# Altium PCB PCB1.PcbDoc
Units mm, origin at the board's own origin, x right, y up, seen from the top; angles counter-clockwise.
Board outline 30.4 x 31.22 mm, 2 copper layers (Top Layer, Bottom Layer); 47 components, 33 nets, 158 pads, 139 vias.
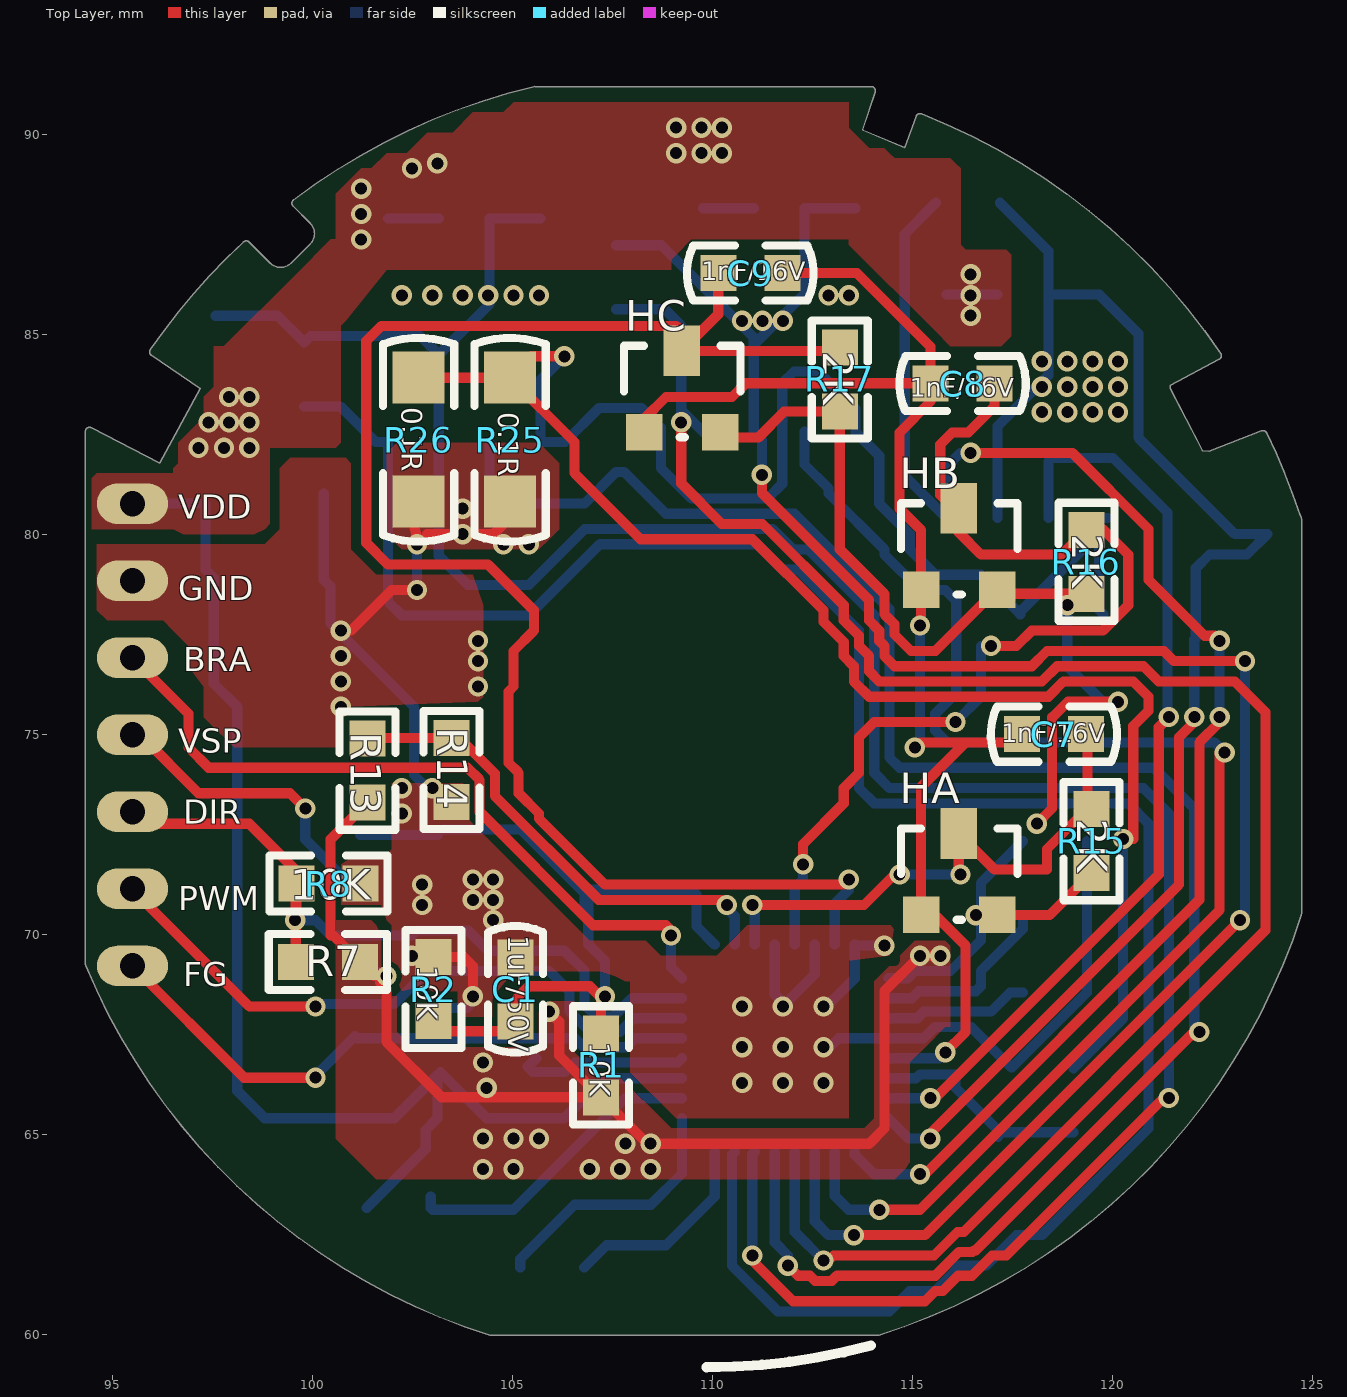
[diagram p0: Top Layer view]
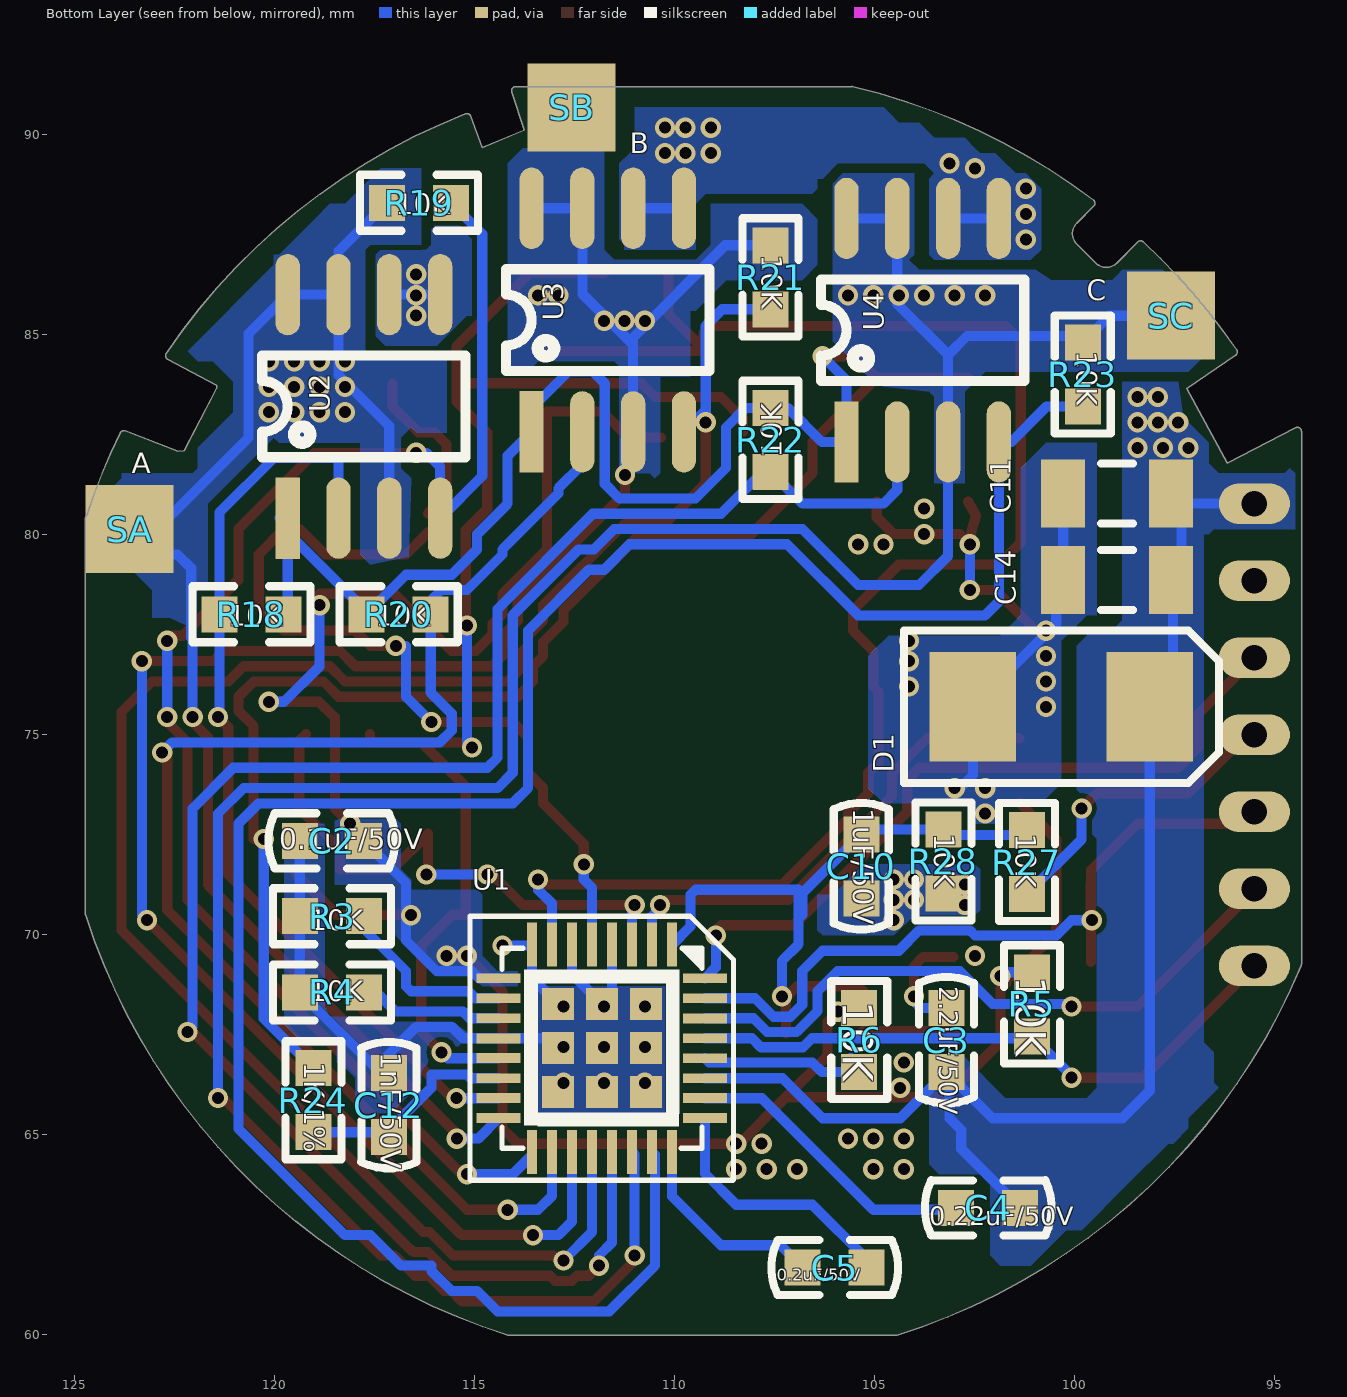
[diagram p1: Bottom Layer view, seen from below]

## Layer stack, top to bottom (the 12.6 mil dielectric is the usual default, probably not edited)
Top Solder: solder mask 0.0102, Solder Resist, Dk 3.5
Top Layer: signal copper 0.0356
Dielectric 1: dielectric 0.32, FR-4, Dk 4.8
Bottom Layer: signal copper 0.0356
Bottom Solder: solder mask 0.0102, Solder Resist, Dk 3.5

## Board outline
94.333,69.224 cw(c94.428,69.263) 94.326,69.263 94.326,82.578 cw(c94.428,82.578) 94.475,82.669 94.474,82.669 94.475,82.669 96.186,81.785 97.199,83.648 95.975,84.48 cw(c96.032,84.564) 95.948,84.622 cw(c109.296,75.438) 98.276,87.315 cw(c98.345,87.24) 98.423,87.306 98.945,86.784 ccw(c98.873,86.712) 98.945,86.784 ccw(c99.206,87.044) 99.466,86.784 99.945,87.263 ccw(c100.017,87.191) 99.945,87.263 ccw(c99.685,87.523) 100.053,87.523 ccw(c99.685,87.523) 99.945,87.783 cw(c100.017,87.856) 99.945,87.784 99.945,87.783 99.518,88.211 cw(c99.59,88.283) 99.528,88.364 cw(c109.296,75.438) 105.538,91.198 cw(c105.562,91.099) 105.581,91.199 113.97,91.199 cw(c113.97,91.097) 114.072,91.097 cw(c113.97,91.097) 114.067,91.065 113.753,90.113 114.812,89.671 115.092,90.455 cw(c115.188,90.421) 115.226,90.516 cw(c109.296,75.438) 122.708,84.529 cw(c122.623,84.471) 122.725,84.471 cw(c122.623,84.471) 122.671,84.381 121.45,83.733 121.45,83.654 122.252,82.1 122.414,82.082 123.73,82.59 cw(c123.767,82.495) 123.859,82.54 cw(c109.296,75.438) 124.696,80.473 cw(c124.626,80.399) 124.728,80.399 124.728,70.518 ccw(c124.626,70.518) 124.728,70.52 124.728,70.518 cw(c124.626,70.518) 124.723,70.487 cw(c109.296,75.438) 114.164,59.985 cw(c114.133,60.082) 114.133,59.98 104.494,59.98 cw(c104.469,60.079) 104.439,59.981 cw(c109.296,75.438)

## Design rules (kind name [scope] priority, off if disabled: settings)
Clearance [All] p1: gap=0.127
PolygonConnect [All] p1: connectstyle=Direct reliefconductorwidth=0.254 reliefentries=4 polygonreliefangle="90 Angle" airgapwidth=0.254
RoutingVias [All] p1: holewidth=0.711 width=1.27 viastyle="Through Hole" minholewidth=0.711 minwidth=1.27 maxholewidth=0.711 maxwidth=1.27
SilkToSilkClearance [All] p1: silktosilkclearance=0.051
SolderMaskExpansion [All] p1: expansion=0.102
Width [All] p1: maxlimit=0.254 minlimit=0.254 preferedwidth=0.254
29 further rules are at their usual default settings.

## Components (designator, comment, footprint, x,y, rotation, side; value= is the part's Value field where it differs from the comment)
C1 "1uF/50V" C0603 101.981,68.326 r180 top
C2 "0.1uF/50V" C0603 118.872,75.438 r90 bottom
C3 "2.2uF/50V" C0603 106.299,67.056 r0 bottom
C4 "0.22uF/50V" C0603 101.854,60.071 r270 bottom
C5 "0.2uF/50V" C0603 106.299,64.77 r90 bottom
C7 "1nF/16V" C0603 118.237,78.105 r90 top
C8 "1nF/16V" C0603 115.951,86.868 r90 top
C9 "1nF/16V" C0603 111.252,83.439 r270 top
C10 "1uF/50V" C0603 102.235,72.009 r180 bottom
C11 "22uF/25V" C1206 98.933,81.026 r180 bottom
C12 "1nF/50V" C0603 114.046,66.04 r180 bottom
C14 "22uF/25V" C1206 98.933,78.867 r180 bottom
D1 "24V/Zener" SMB 100.33,75.692 r180 bottom
HA "HALL_SOT23-3" SOT-23 119.507,70.866 r0 top locked
HB "HALL_SOT23-3" SOT-23 119.507,78.994 r0 top locked
HC "HALL_SOT23-3" SOT-23 112.582,82.931 r0 top locked
R1 "10K" R0603 105.537,65.278 r180 top
R2 "10K" R0603 101.346,67.183 r180 top
R3 "10K" R0603 120.015,72.136 r90 bottom
R4 "10K" R0603 120.015,70.231 r90 bottom
R5 "10K" R0603 102.743,66.802 r0 bottom
R6 "10K" R0603 107.061,65.913 r0 bottom
R7 "" R0603 98.933,70.993 r90 top
R8 "10K" R0603 101.854,69.596 r270 top
R13 "" R0603 99.695,72.644 r180 top
R14 "" R0603 105.156,75.565 r0 top
R15 "2K" R0603 121.158,73.787 r0 top
R16 "2K" R0603 121.031,80.772 r0 top
R17 "2K" R0603 111.506,82.423 r180 top
R18 "10K" R0603 119.126,76.327 r270 bottom
R19 "10K" R0603 114.935,86.614 r270 bottom
R20 "10K" R0603 115.443,76.327 r270 bottom
R21 "10K" R0603 105.918,87.884 r180 bottom
R22 "10K" R0603 105.918,83.82 r180 bottom
R23 "10K" R0603 101.473,82.55 r0 bottom
R24 "1K/1%" R0603 117.348,67.31 r180 bottom
R25 "0.1R" R1206 107.188,82.296 r0 top
R26 "0.1R" R1206 104.902,82.296 r0 top
R27 "10K" R0603 102.87,70.358 r0 bottom
R28 "10K" R0603 101.6,73.279 r180 bottom
SA "" cp1 129.921,80.137 r0 top
SB "" cp1 118.872,90.678 r0 top
SC "" cp1 103.886,85.471 r0 top
U1 "SDC9270_QFN32" "QFN32 (5*5)" 111.887,72.39 r90 bottom
U2 "MOS" SOP-8 123.571,83.058 r0 bottom
U3 "MOS" SOP-8 117.475,85.217 r0 bottom
U4 "MOS" SOP-8 109.601,84.963 r0 bottom

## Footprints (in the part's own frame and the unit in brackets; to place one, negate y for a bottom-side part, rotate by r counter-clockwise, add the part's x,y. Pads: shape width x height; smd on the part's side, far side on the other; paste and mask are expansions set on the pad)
C0603 [mm]
  rect 0.9x0.9 smd: 1(-3.096,0.496) 2(-3.096,-1.104)
  silkscreen extent -3.78,-1.88 -2.41,1.28
C1206 [mm] "Chip Capacitor, Body 3.2x1.6mm, IPC High Density"
  rect 1.1x1.7 smd: 1(-1.35,0) 2(1.35,0)
  silkscreen extent -0.4,-0.75 0.4,0.75, body extent -1.7,-0.9 1.7,0.9, height 1.3
cp1 [mm]
  rect 2.2x2.2 smd far side: 1(-6.3,0)
"QFN32 (5*5)" [mm]
  rect 1.1x0.25 smd: 1(-2.643,-1.828) 2(-2.643,-1.328) 3(-2.643,-0.828) 4(-2.643,-0.328) 5(-2.643,0.172) 6(-2.643,0.672) 7(-2.643,1.172) 8(-2.643,1.672) 17(-7.823,1.672) 18(-7.823,1.172) 19(-7.823,0.672) 20(-7.823,0.172) 21(-7.823,-0.328) 22(-7.823,-0.828) 23(-7.823,-1.328) 24(-7.823,-1.828)
  rect 0.25x1.1 smd: 9(-3.483,2.512) 10(-3.983,2.512) 11(-4.483,2.512) 12(-4.983,2.512) 13(-5.483,2.512) 14(-5.983,2.512) 15(-6.483,2.512) 16(-6.983,2.512) 25(-6.983,-2.648) 26(-6.483,-2.648) 27(-5.983,-2.648) 28(-5.483,-2.648) 29(-4.983,-2.648) 30(-4.483,-2.648) 31(-3.983,-2.648) 32(-3.483,-2.648)
  rect 0.8x0.8 smd: 33(-6.333,-1.178) 33(-6.333,-0.078) 33(-6.333,1.022) 33(-5.233,-1.178) 33(-5.233,-0.078) 33(-5.233,1.022) 33(-4.133,-1.178) 33(-4.133,-0.078) 33(-4.133,1.022)
  silkscreen extent -8.53,-3.36 -1.93,3.22
R0603 [mm]
  rect 0.9x0.9 smd: 1(-1.679,-0.653) 2(-1.679,-2.253)
  silkscreen extent -2.38,-2.93 -0.98,0.02
R1206 [mm]
  rect 1.3x1.3 smd: 1(-2.244,-1.475) 2(-2.244,1.625)
  silkscreen extent -3.13,-2.47 -1.35,2.62
SMB [mm]
  rect 2.159x2.743 smd: 1(-2.21,0) 2(2.21,0)
  silkscreen extent -3.94,-1.91 3.94,1.91
SOP-8 [mil]
  rect 24x80 smd: 1(-153.56,104.3)
  oval 24x80 smd: 2(-203.56,104.3) 3(-253.56,104.3) 4(-303.56,104.3) 5(-303.56,-115.7) 6(-253.56,-115.7) 7(-203.56,-115.7) 8(-153.56,-115.7)
  silkscreen extent -329,-56 -129,44
SOT-23 [mil]
  rect 36x36 smd: 1(-93.79,-14.61) 3(-168.79,-14.61)
  rect 36x50 smd: 2(-131.79,65.39)
  silkscreen extent -189,-20 -74,70

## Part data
C1 C7 C8 C9 C10 C11 C12 C14: library part C0603, "C0603"
C2 C4 C5: library part C0805, "C0805"
C3: library part C1206, "C1206"
D1: library part Zener_SOD-123, "Zener Diode"
R1 R2 R3 R4 R5 R6 R7 R8 R13 R14 R15 R16 R17 R24 R27 R28: library part R0603, "R0603"
R18 R19 R20 R21 R22 R23: library part R1_0603
R25 R26: library part R2512
SA SB SC: library part CON1, "Connector"

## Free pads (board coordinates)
  oval 1.778x1.016 hole 0.635: 1(95.504,69.215) 1(95.504,71.141) 1(95.504,73.067) 1(95.504,74.993) 1(95.504,76.92) 1(95.504,78.846) 1(95.504,80.772)

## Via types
v1: diameter 0.508, hole 0.3, Top Layer to Bottom Layer, 139 vias

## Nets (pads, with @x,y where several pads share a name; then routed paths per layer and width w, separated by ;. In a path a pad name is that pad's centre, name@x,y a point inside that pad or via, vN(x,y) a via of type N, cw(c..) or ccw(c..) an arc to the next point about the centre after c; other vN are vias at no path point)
BRAKE: pad.1@95.504,76.92 U1.32 | length 18.6
  Top Layer w0.254: pad.1@95.504,76.92 96.901,75.523 96.901,74.676 97.409,74.168 103.88,74.168 104.181,73.867 104.181,73.067 107.017,70.231 108.839,70.231 108.966,70.104 v1(108.966,69.977)
  Bottom Layer w0.254: v1(108.966,69.977) 108.966,69.18 U1.32
CP1: C5.1 U1.24 | length 5.1
  Bottom Layer w0.254: C5.1 107.351,62.23 108.839,62.23 110.059,63.45 U1.24
CP2: C5.2 U1.25 | length 6.5
  Bottom Layer w0.254: C5.2 105.195,61.888 106.553,63.246 108.458,63.246 109.239,64.027 U1.25
DIR: pad.1@95.504,73.067 R7.1 R8.2 U1.31 | length 19.4
  Top Layer w0.254: pad.1@95.504,73.067 95.8,72.771 98.425,72.771 99.586,71.61 R7.1 ; v1(99.568,70.358) 99.601,70.391 R8.2
  Bottom Layer w0.254: v1(99.568,70.358) 100.076,70.358 100.457,69.977 102.489,69.977 102.616,70.104 103.886,70.104 104.394,69.596 106.299,69.596 106.807,69.088 106.807,68.243 107.105,67.945 107.525,67.945 107.987,68.407 U1.31
FG: pad.1@95.504,69.215 R5.1 U1.29 | length 15.6
  Top Layer w0.254: pad.1@95.504,69.215 98.298,66.421 v1(100.076,66.421)
  Bottom Layer w0.254: v1(100.076,66.421) 100.076,66.467 R5.1 101.112,67.407 106.565,67.407 106.789,67.183 107.841,67.183 108.065,67.407 U1.29
GHA: R19.1 U1.17 U2.4 | length 38
  Top Layer w0.254: v1(115.189,64.008) 115.316,64.008 122.174,70.866 122.174,74.803 122.682,75.311 v1(122.682,75.438) ; v1(116.459,82.042) 118.999,82.042 120.904,80.137 120.904,78.867 122.301,77.47 122.555,77.47 v1(122.682,77.343)
  Bottom Layer w0.254: U1.17 113.559,64.495 114.046,64.008 v1(115.189,64.008) ; R19.1 114.808,87.513 114.808,81.461 U2.4 115.86,81.697 116.205,82.042 v1(116.459,82.042) ; v1(122.682,75.438) v1(122.682,77.343)
GHB: R21.2 U1.20 U3.4 | length 47.3
  Top Layer w0.254: v1(109.22,82.804) 109.22,81.28 110.236,80.264 111.252,80.264 113.284,78.232 113.284,77.851 113.665,77.47 113.665,77.216 113.919,76.962 113.919,76.581 114.173,76.327 118.237,76.327 118.618,76.708 120.777,76.708 121.158,76.327 123.063,76.327 123.825,75.565 123.825,70.104 116.284,62.563 116.126,62.563 115.539,61.976 113.03,61.976 v1@112.903,61.849 ; v1@112.649,61.849 v1(112.776,61.849)
  Bottom Layer w0.254: R21.2 108.806,85.631 109.22,85.217 109.22,83.112 ; v1(109.22,82.804) 109.22,83.112 ; U3.4 109.22,83.112 ; U1.20 112.059,62.566 v1(112.776,61.849)
GHC: R23.1 U1.23 U4.4 | length 54.9
  Bottom Layer w0.254: R23.1 100.693,83.203 101.582,82.314 U4.4 101.89,78.323 102.235,77.978 105.41,77.978 107.188,79.756 111.125,79.756 111.76,79.121 112.141,79.121 113.665,77.597 113.665,73.66 114.046,73.279 120.396,73.279 120.904,72.771 120.904,65.151 118.237,62.484 117.602,62.484 116.84,61.722 116.078,61.722 116.078,61.595 115.57,61.087 114.935,61.087 114.427,60.579 111.633,60.579 110.49,61.722 110.49,64.498 U1.23
GLA: R18.2 U1.15 U2.2 | length 23.3
  Top Layer w0.254: v1(115.449,65.907) 115.564,65.907 121.158,71.501 121.158,75.184 v1(121.412,75.438)
  Bottom Layer w0.254: U1.15 v1(115.449,65.907) ; U2.2 118.4,81.824 118.491,81.915 120.015,81.915 121.379,80.551 R18.2 v1@121.379,75.344
GLB: R20.1 U1.18 U3.2 | length 35.1
  Top Layer w0.254: v1(114.173,63.119) 115.189,63.119 122.682,70.612 122.682,74.549 v1(122.809,74.549)
  Bottom Layer w0.254: U3.2 112.304,81.752 112.903,81.153 112.903,81.026 114.3,79.629 114.3,79.502 115.189,78.613 115.824,78.613 116.096,78.341 R20.1 116.096,76.047 115.57,75.521 115.57,75.101 115.868,74.803 122.555,74.803 v1(122.809,74.549) ; U1.18 113.059,63.471 113.411,63.119 v1(114.173,63.119)
GLC: R22.2 U1.21 U4.2 | length 46.8
  Top Layer w0.254: v1(111.887,61.722) 112.141,61.468 112.439,61.468 112.566,61.341 112.986,61.341 113.113,61.468 115.57,61.468 116.163,62.061 116.506,62.061 116.548,62.103 116.586,62.103 122.174,67.691 v1(122.174,67.564)
  Bottom Layer w0.254: U4.2 104.43,81.117 104.775,80.772 106.802,80.772 R22.2 107.79,81.567 108.839,80.518 112.045,80.518 114.427,78.136 114.427,74.422 114.681,74.168 121.031,74.168 122.047,73.152 122.047,67.691 v1(122.174,67.564) ; U1.21 111.559,62.304 111.887,61.976 v1(111.887,61.722)
GND: 
HA: C7.2 HA.2 R15.1 U1.3 | length 13.8
  Top Layer w0.254: v1@111.125,70.739 113.792,70.739 114.554,71.501 v1(114.681,71.501) ; v1@116.159,71.547 HA.2@116.159,72.518 ; HA.2 HA.2@116.159,72.518 ; C7.2@119.214,75.009 119.38,74.843 119.38,73.152 118.364,72.136 118.364,71.628 117.049,71.628 HA.2@116.159,72.518
  Bottom Layer w0.254: v1(110.998,70.739) 111.059,70.678 U1.3 ; v1(114.681,71.501) v1(116.205,71.501)
HB: C8.2 HB.2 R16.1 U1.5 | length 24.9
  Top Layer w0.254: v1(112.268,71.755) 112.268,72.263 113.284,73.279 113.284,73.66 113.665,74.041 113.665,74.93 114.046,75.311 v1(116.078,75.311) ; HB.2@116.159,80.056 116.713,79.502 118.735,79.502 R16.1 119.779,80.119 120.396,79.502 120.396,78.232 119.761,77.597 117.983,77.597 117.602,77.216 v1(116.967,77.216) ; HB.2@116.159,80.528 115.697,80.99 115.697,82.252 115.995,82.55 116.398,82.55 117.055,83.207 C8.2
  Bottom Layer w0.254: U1.5 112.059,71.165 112.268,71.374 v1(112.268,71.755) ; v1(116.078,75.311) 116.713,75.946 v1@116.713,77.216
HC: C9.2 HC.2 R17.2 U1.7 | length 40.8
  Top Layer w0.254: C9.2 110.148,85.506 HC.2@109.273,84.631 ; R17.2 113.101,84.592 HC.2 HC.2@109.273,84.631 ; v1(113.411,71.374) 113.284,71.247 107.315,71.247 105.664,72.898 105.664,73.025 105.156,73.533 105.156,74.041 104.902,74.295 104.902,76.073 105.029,76.2 105.029,77.089 105.537,77.597 105.537,78.105 104.394,79.248 101.89,79.248 101.346,79.792 101.346,84.836 101.727,85.217 109.093,85.217 109.273,85.037 HC.2@109.273,84.631
  Bottom Layer w0.254: U1.7 113.059,70.768 113.411,71.12 v1(113.411,71.374)
ILIMIT: C12.2 R24.2 U1.14 | length 5.5
  Bottom Layer w0.254: U1.14 115.091,66.407 115.189,66.504 116.078,66.504 116.078,66.167 117.142,65.103 C12.2 ; C12.2@117.262,65.057 R24.2
ISENSE: R18.1 R20.2 R22.1 R24.1 R25.2 R26.2 U2.1 U3.1 U4.1 | length 63
  Top Layer w0.254: R26.2 R25.2 ; v1(106.299,84.455) 105.478,84.455 R25.2 ; v1(120.269,72.39) 120.523,72.39 120.523,75.215 120.904,75.596 120.904,75.946 120.523,76.327 118.776,76.327 118.395,75.946 113.919,75.946 113.538,76.327 113.538,76.708 113.284,76.962 113.284,77.312 112.776,77.82 112.776,78.105 110.998,79.883 108.204,79.883 106.553,81.534 106.553,82.312 R25.2
  Bottom Layer w0.254: v1(106.299,84.455) 105.7,83.856 U4.1 106.317,82.314 107.17,83.167 R22.1 108.222,83.167 108.712,82.677 108.712,81.661 109.474,80.899 111.379,80.899 111.746,81.266 111.746,83.779 112.041,84.074 112.649,84.074 113.574,83.149 U3.1 114.173,81.969 114.173,80.772 114.935,80.01 114.935,79.629 115.57,78.994 116.713,78.994 R20.2@117.696,78.011 ; R20.2 R20.2@117.696,78.011 ; R24.1 120.269,67.899 v1(120.269,72.39) ; R18.1 119.67,78.115 U2.1@119.67,80.046 ; U2.1@119.87,80.409 U2.1 U2.1@119.67,80.046 ; R20.2@117.696,78.011 117.696,78.072 U2.1@119.67,80.046
LEAD: R13.2 R14.1 U1.2 | length 12.1
  Top Layer w0.254: R13.2 101.389,74.912 R14.1 103.675,74.912 104.562,74.025 104.562,73.461 107.157,70.866 110.236,70.866 v1(110.363,70.739)
  Bottom Layer w0.254: v1(110.363,70.739) 110.363,70.656 110.559,70.46 U1.2
MODE: R3.2 U1.10 | length 4.6
  Bottom Layer w0.254: U1.10 114.985,68.407 115.159,68.58 116.586,68.58 116.713,68.707 116.713,69.088 117.762,70.137 R3.2
NetP1_3: pad.1@95.504,74.993 R27.1 | length 7.8
  Top Layer w0.254: pad.1@95.504,74.993 95.695,74.993 97.155,73.533 99.441,73.533 v1(99.822,73.152)
  Bottom Layer w0.254: v1(99.822,73.152) 99.822,72.38 R27.1
NFLT: R6.1 U1.28 | length 4.4
  Bottom Layer w0.254: R6.1@105.596,66.907 105.382,66.693 105.509,66.566 106.317,66.566 106.553,66.802 109.134,66.802 U1.28
PGND: C7.1 C8.1 C9.1 HA.3 HB.3 HC.3 U1.13 | length 36.3
  Top Layer w0.254: HC.3 108.295,82.895 108.839,83.439 110.49,83.439 110.831,83.78 C8.1@115.455,83.78 ; C9.1 113.617,86.535 115.455,84.697 C8.1@115.455,83.78 ; v1(115.062,74.676) 115.189,74.803 116.332,74.803 ; v1@115.22,77.755 HB.3 115.22,80.106 114.681,80.645 114.681,82.55 115.455,83.324 C8.1 C8.1@115.455,83.78 ; v1(115.824,67.056) 116.332,67.564 116.332,69.723 115.56,70.495 HA.3 115.22,73.691 116.332,74.803 ; C7.1@117.614,75.009 117.614,74.803 116.332,74.803
  Bottom Layer w0.254: U1.13 115.675,66.907 v1(115.824,67.056) ; v1(115.062,74.676) 115.189,74.803 v1(115.189,77.724)
PWM: pad.1@95.504,71.141 U1.30 | length 16.4
  Top Layer w0.254: pad.1@95.504,71.141 95.504,71.12 98.425,68.199 v1(100.076,68.199)
  Bottom Layer w0.254: v1(100.076,68.199) 100.141,68.264 102.046,68.264 102.87,69.088 105.918,69.088 106.426,68.58 106.426,68.085 106.947,67.564 107.683,67.564 108.026,67.907 U1.30
PWMIN: 
SA: R19.2 SA.1 U1.16 U2.3 U2.7 U2.8 | length 39
  Top Layer w0.254: v1(115.443,64.897) 115.316,64.897 121.666,71.247 121.666,74.93 122.047,75.311 v1(122.047,75.438)
  Bottom Layer w0.254: U1.16 114.909,64.897 v1(115.443,64.897) ; U2.3 117.13,82.713 118.4,83.983 U2.7 ; R19.2 118.4,87.081 U2.7 ; v1(122.047,75.438) 122.047,77.379 122.083,77.415 122.083,79.157 122.428,79.502 123.367,79.502 123.875,80.01 123.063,80.01 120.65,82.423 120.65,85.017 U2.8 U2.7
  other v1: 118.237,83.058 118.872,83.058 119.507,83.058 120.142,83.058 118.237,83.693 118.872,83.693 119.507,83.693 120.142,83.693 118.237,84.328 118.872,84.328 119.507,84.328 120.142,84.328
SB: R21.1 SB.1 U1.19 U3.3 U3.7 U3.8 | length 50.6
  Top Layer w0.254: v1(111.238,81.494) 111.238,81.04 113.919,78.359 113.919,77.851 114.173,77.597 114.173,77.343 114.3,77.216 114.3,76.962 114.554,76.708 117.983,76.708 118.364,77.089 121.285,77.089 121.539,76.835 v1(123.317,76.835) ; v1(113.538,62.484) 115.316,62.484 v1(123.19,70.358)
  Bottom Layer w0.254: R21.1 108.73,87.231 111.034,84.927 111.034,84.745 ; v1(111.238,81.494) 111.238,82.365 U3.3 111.034,84.745 ; U1.19 112.559,62.828 112.903,62.484 v1(113.538,62.484) ; U3.8 U3.7 112.304,86.015 111.034,84.745 ; v1(123.19,70.358) 123.317,70.485 v1(123.317,76.835)
  other v1: 110.744,85.344 111.252,85.344 111.76,85.344 112.903,85.979 113.411,85.979
SC: R23.2 SC.1 U1.22 U4.3 U4.7 U4.8 | length 63.7
  Top Layer w0.254: v1(110.998,61.976) 110.998,61.849 112.014,60.833 115.316,60.833 115.57,61.087 115.759,61.087 116.14,61.468 116.49,61.468 116.998,61.976 117.348,61.976 121.412,66.04 v1(121.412,65.913)
  Bottom Layer w0.254: SC.1 99.126,85.471 R23.2 99.954,84.963 102.689,84.963 103.16,84.491 ; U4.8 U4.7 104.43,85.761 103.16,84.491 ; v1(110.998,61.976) 110.998,64.506 U1.22 ; v1(121.412,65.913) 121.412,73.025 120.777,73.66 114.427,73.66 114.046,74.041 114.046,77.978 112.395,79.629 112.014,79.629 111.506,80.137 106.807,80.137 105.41,78.74 103.886,78.74 103.16,79.466 U4.3 103.16,84.491
  other v1: 102.235,85.979 102.997,85.979 103.759,85.979 104.394,85.979 105.029,85.979 105.664,85.979
SGND: C1.2 C2.1 C3.2 C10.2 C11.1 C12.1 C14.1 D1.1 pad.1@95.504,78.846 R2.2 R3.1 R4.1 R8.1 R14.2 R25.1 R26.1 R28.2 U1.4 U1.6 U1.8 U1.12 U1.33 | length 36.2
  Top Layer w0.254: v1(100.711,77.597) 100.965,77.597 101.981,78.613 v1(102.616,78.613) ; v1(102.616,79.756) 102.658,79.798 102.466,80.477 R26.1 ; 102.87,80.01 v1(103.759,80.01) 104.521,80.01 104.944,80.433 R25.1 ; R2.2 103.792,69.436 104.013,69.215 v1(104.013,68.453)
  Bottom Layer w0.254: C11.1 C14.1 100.457,78.693 100.457,77.775 D1.1 102.54,73.99 102.87,73.66 v1(102.997,73.66) ; v1(102.616,78.613) v1(102.616,79.756) ; C3.2 103.847,68.16 104.013,68.326 v1(104.013,68.453) ; U1.4 111.559,68.507 111.809,68.257 112.559,69.007 U1.6 ; U1.33@112.909,67.157 113.159,67.407 U1.12 115.286,67.407 115.57,67.691 116.459,67.691 117.475,66.675 117.485,66.675 R4.1 ; U1.33@112.909,68.257 113.559,68.907 U1.8 113.583,69.723 v1(114.3,69.723) ; R4.1@119.368,68.558 C2.1
  other v1: 110.744,66.294 111.76,66.294 112.776,66.294 110.744,67.183 111.76,67.183 112.776,67.183 110.744,68.199 111.76,68.199 112.776,68.199 102.489,69.469 104.521,70.358 102.743,70.739 104.013,70.866 104.521,70.866 102.743,71.247 104.013,71.374 104.521,71.374 102.235,73.025 102.235,73.66 100.711,75.692 104.14,76.2 100.711,76.327 104.14,76.835 100.711,76.962 104.14,77.343 104.775,79.756 105.41,79.756 103.759,80.645
SREF: C1.1 C10.1 R1.2 R2.1 R27.2 R28.1 U1.1 | length 20.1
  Top Layer w0.254: R2.1@102.898,67.582 C1.1@105.301,67.582 ; C1.1 105.077,68.374 105.41,68.707 106.934,68.707 107.188,68.453 v1(107.315,68.453) 107.216,68.354 R1.2
  Bottom Layer w0.254: R27.2@101.191,72.484 R28.1@103.137,72.484 ; R28.1 105.21,72.626 C10.1 106.807,71.029 106.807,70.485 ; v1(107.315,68.453) 107.315,69.342 106.898,69.759 106.898,71.12 109.474,71.12 109.601,70.993 109.601,70.205 U1.1
TEST: R4.2 U1.11 | length 3.6
  Bottom Layer w0.254: U1.11 115.12,67.907 115.285,68.072 116.967,68.072 117.447,68.552 R4.2
VCP: C4.2 U1.26 | length 7.7
  Bottom Layer w0.254: C4.2@102.958,63.452 C4.2 103.005,63.119 105.029,63.119 107.817,65.907 U1.26
VDD: C3.1 C4.1 C11.2 C14.2 D1.2 pad.1@95.504,80.772 U1.27 U2.5 U2.6 U3.5 U3.6 U4.5 U4.6 | length 37.5
  Bottom Layer w0.254: pad.1@95.504,80.772 97.329,80.772 97.329,79.121 97.536,78.914 97.536,76.276 D1.2 98.12,66.091 98.806,65.405 102.049,65.405 C3.1@103.124,66.48 ; C4.1 102.834,64.643 102.834,65.115 103.124,65.405 C3.1@103.124,66.48 ; U4.5 U4.6 ; U1.27 107.301,66.407 106.299,65.405 104.358,65.405 C3.1 C3.1@103.124,66.48 ; U3.5 U3.6 ; U2.5 U2.6
  other v1: 97.155,82.169 97.79,82.169 98.425,82.169 97.409,82.804 97.917,82.804 98.425,82.804 97.917,83.439 98.425,83.439 116.459,85.471 116.459,85.979 116.459,86.505 101.219,87.376 101.219,88.011 101.219,88.646 102.489,89.154 103.124,89.281 109.093,89.535 109.728,89.535 110.236,89.535 109.093,90.17 109.728,90.17 110.236,90.17
VREF: C2.2 HA.1 HB.1 HC.1 R1.1 R5.2 R6.2 R7.2 R13.1 R15.2 R16.2 R17.1 U1.9 | length 60.6
  Top Layer w0.254: R13.1 100.457,72.38 100.457,69.977 100.523,69.977 R7.2 101.539,68.961 v1(101.854,68.961) ; v1@101.696,68.803 101.854,68.646 101.854,67.31 103.233,65.931 R1.1 ; v1(105.918,68.072) 106.172,67.818 106.172,66.975 R1.1 ; HC.1@110.337,82.423 111.146,82.423 111.799,83.076 R17.1 113.185,79.632 114.3,78.517 114.3,78.009 114.554,77.755 114.554,77.501 114.966,77.089 115.57,77.089 HB.1@117.104,78.623 ; v1(115.697,69.469) v1(115.189,69.469) 114.3,68.58 114.3,65.151 113.919,64.77 108.377,64.77 R1.1 ; v1@116.596,70.495 HA.1 ; HA.1@117.135,70.485 118.43,70.485 R15.2 ; HB.1@117.229,78.519 118.872,78.519 ; v1(118.11,72.771) 118.491,73.152 118.491,75.438 118.51,75.438 118.891,75.819 v1(120.142,75.819) ; v1(118.872,78.232) R16.2@119.065,78.232
  Bottom Layer w0.254: R5.2 101.76,69.055 v1(101.854,68.961) ; U1.9 114.881,68.907 115.062,69.088 115.951,69.088 116.713,69.85 116.713,71.287 C2.2 ; v1(118.872,78.232) 118.872,76.708 119.761,75.819 v1(120.142,75.819)
  other v1: 104.267,64.135 105.029,64.135 106.934,64.135 107.696,64.135 108.458,64.135 107.823,64.77 108.458,64.77 104.267,64.897 105.029,64.897 105.664,64.897 104.358,66.167 104.267,66.802 116.586,70.485

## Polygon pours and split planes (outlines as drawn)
SGND on Bottom Layer "SGND" (solid, remove dead copper, pour order 30): 100.711,82.169 101.219,81.661 101.346,81.534 101.346,77.978 101.854,77.47 104.013,77.47 104.521,77.47 104.648,77.47 105.029,77.089 105.156,76.962 105.156,73.787 105.156,73.66 104.775,73.279 102.616,73.279 102.616,72.771 101.854,72.771 101.854,73.279 100.838,73.279 100.457,73.66 100.33,73.787 100.33,77.343 99.695,77.978 99.441,77.978 99.441,82.296 100.711,82.296 101.346,81.661 101.346,81.534
VREF on Bottom Layer "VREF" (solid, remove dead copper, pour order 24): 113.919,68.707 114.808,68.707 114.935,68.834 115.062,68.961 115.951,68.961 116.84,69.85 117.094,70.104 117.094,70.993 117.094,71.247 118.491,71.247 118.491,73.025 118.364,72.898 116.967,72.898 116.84,72.771 116.84,71.628 116.586,71.374 116.586,71.12 115.951,71.12 115.824,70.993 115.951,71.12 114.935,71.12 114.808,70.993 114.808,70.485 114.808,69.469 114.681,69.342 114.427,69.088 113.919,69.088
SGND on Bottom Layer "SGND" (solid, remove dead copper, pour order 22): 105.283,71.755 106.045,70.993 106.426,70.993 106.426,70.104 106.299,69.977 104.648,69.977 104.521,69.977 104.013,70.485 102.489,70.485 102.362,70.612 102.362,71.628 102.489,71.755 105.283,71.755
SGND on Bottom Layer "SGND" (solid, remove dead copper, pour order 20): 113.359,68.707 113.411,68.655 113.411,65.532 110.236,65.532 110.236,68.707 111.76,68.707 113.359,68.707 113.411,68.759
VDD on Bottom Layer "VDD" (solid, remove dead copper, pour order 12): 98.806,83.82 98.806,77.851 99.06,77.597 99.314,77.597 99.568,77.597 99.949,77.216 99.949,73.66 99.949,72.898 99.568,72.517 99.441,72.39 99.441,72.009 99.441,66.167 99.695,65.913 101.346,65.913 101.727,65.913 102.743,66.929 103.632,66.929 103.632,64.262 103.378,64.008 102.362,64.008 102.108,63.754 102.108,62.611 102.108,61.976 101.854,61.722 101.346,61.722 101.092,61.722 100.203,62.611 99.822,62.611 98.679,63.754 97.663,64.77 97.536,64.77 97.155,65.151 97.155,65.278 97.155,65.405 96.393,66.167 96.52,66.294 96.52,66.929 96.52,67.056 96.647,67.183 96.774,67.31 96.774,80.01 96.647,80.01 96.52,80.137 94.488,80.137 94.488,81.534 94.615,81.661 94.742,81.534 96.393,81.534 96.647,81.788 96.647,82.169 96.647,82.296 97.028,82.677 97.282,82.931 97.409,83.82
VDD on Bottom Layer "VDD" (solid, remove dead copper, pour order 10): 111.252,87.122 111.252,87.249 111.379,87.376 111.379,89.281 111.125,89.535 110.998,89.662 110.998,90.678 105.664,90.678 105.537,90.678 105.41,90.678 105.156,90.678 104.775,90.678 104.648,90.551 104.394,90.297 104.013,90.297 103.886,90.297 103.505,89.916 102.997,89.916 102.743,89.916 102.489,89.662 102.362,89.535 102.235,89.535 101.981,89.535 101.854,89.408 101.473,89.027 101.219,89.027 100.838,88.646 100.838,87.376 100.838,87.122 101.092,86.868 101.346,86.868 103.505,86.868 103.632,86.995 103.632,87.249 103.632,88.9 103.505,89.027 103.759,89.281 103.886,89.281 105.918,89.281 106.299,88.9 106.426,88.9 106.426,88.646 106.553,88.519 109.093,88.519 109.22,88.519 109.347,88.392 109.474,88.265 109.474,87.122
SC on Bottom Layer "SC" (solid, remove dead copper, pour order 8): 105.791,89.027 106.045,88.773 106.045,84.836 105.918,84.709 105.029,83.82 104.775,83.693 103.632,83.566 103.505,83.439 103.505,81.28 102.743,81.28 102.743,83.566 102.362,83.947 102.235,84.074 99.441,84.074 97.155,84.074 96.52,84.709 96.774,84.963 96.774,85.217 96.774,85.598 97.79,86.614 98.298,86.614 98.806,86.614 98.933,86.487 99.06,86.36 99.695,86.36 100.584,86.36 100.965,86.614 101.092,86.614 103.886,86.614 104.14,86.868 104.013,86.995 104.013,89.027
SB on Bottom Layer "SB" (solid, remove dead copper, pour order 6): 113.538,90.932 113.538,89.662 113.792,89.662 114.173,89.281 114.173,84.201 113.538,84.201 113.411,84.328 111.506,84.328 111.379,84.201 111.379,81.534 110.617,81.534 110.49,81.407 110.363,81.534 110.363,83.947 109.601,83.947 109.601,85.598 109.474,85.598 109.093,85.979 108.712,86.36 106.807,86.36 106.426,86.741 106.426,87.884 106.807,88.265 108.839,88.265 109.093,88.265 109.093,87.63 109.093,87.249 109.347,86.995 109.474,86.868 109.728,86.868 111.506,86.868 111.633,86.995 111.76,87.122 111.76,87.249 111.76,91.059 113.538,91.059 113.665,90.932
SA on Bottom Layer "SA" (solid, remove dead copper, pour order 2): 116.332,89.154 117.348,89.154 117.729,88.773 118.237,88.265 118.491,88.265 118.618,88.265 118.999,87.884 119.888,86.995 120.015,86.995 120.015,86.741 122.174,84.582 121.92,84.328 121.539,84.328 121.158,83.947 121.031,83.82 121.031,83.312 121.031,83.058 121.539,82.55 121.92,82.169 121.92,81.915 121.92,81.661 122.047,81.534 123.825,81.534 123.825,81.407 124.079,81.153 124.46,80.772 124.46,79.121 123.571,79.121 123.19,78.74 123.063,78.613 123.063,77.914 122.618,77.914 121.92,77.597 121.92,78.613 121.666,78.74 121.666,80.772 120.015,82.423 119.888,82.296 117.856,82.296 117.856,79.502 117.602,79.248 116.649,79.438 116.586,81.407 116.84,81.661 116.84,82.423 116.586,82.677 116.459,82.55 115.697,82.55 115.697,84.328 115.951,84.582 117.729,84.582 117.729,87.122 117.602,87.249 116.332,87.249
VDD on Bottom Layer "VDD" (solid, remove dead copper, pour order 34): 117.348,87.122 117.475,86.995 117.475,84.836 117.475,84.963 117.221,84.709 115.951,84.709 115.189,85.471 115.062,85.471 115.062,87.376 115.316,87.63 115.316,87.757 115.951,87.757 116.078,87.63 116.078,87.503 116.078,87.249 116.205,87.122 117.348,87.122
SGND on Bottom Layer "SGND" (solid, remove dead copper, pour order 35): 119.507,72.771 119.761,72.771 119.761,67.564 119.761,67.437 119.126,66.802 118.364,66.802 117.602,66.04 117.983,66.421 117.983,65.278 117.983,65.532 117.094,65.532 116.332,66.294 116.205,66.675 115.189,67.183 115.316,67.31 115.189,67.31 115.189,67.564 115.57,67.818 115.951,67.818 117.094,67.818 117.348,67.945 118.618,67.945 118.745,68.199 118.745,72.263 118.745,72.771
VREF on Top Layer "VREF" (solid, remove dead copper, pour order 26): 101.473,70.358 101.6,70.231 101.727,69.977 101.727,68.453 102.108,68.453 102.108,67.564 102.489,67.183 105.664,67.183 105.664,68.072 105.918,68.326 106.553,68.326 106.553,67.056 106.68,66.929 107.061,66.548 107.315,66.548 107.569,66.548 108.966,65.151 109.22,65.151 113.792,65.151 113.919,65.278 114.046,65.405 114.046,65.913 114.046,68.834 115.062,69.85 115.824,69.85 115.951,69.723 115.951,67.691 115.824,67.691 115.316,67.183 114.935,66.802 114.935,64.389 114.935,64.262 114.554,63.881 107.188,63.881 101.6,63.881 100.711,64.77 100.584,64.897 100.584,70.358
SGND on Top Layer "SGND" (solid, remove dead copper, pour order 18): 103.632,73.787 103.759,73.787 103.886,73.66 103.886,72.898 106.934,69.85 108.331,69.85 108.712,69.469 110.109,69.469 110.871,70.231 114.554,70.231 114.427,69.469 113.411,69.342 113.411,66.675 113.411,65.405 113.665,65.405 109.728,65.405 109.093,65.405 108.077,66.421 107.95,66.548 107.95,68.834 107.823,68.834 107.569,68.961 107.188,69.088 105.029,69.088 104.521,68.453 104.521,67.945 103.632,67.945 103.632,68.58 102.997,68.58 102.743,68.707 102.235,68.58 101.981,69.215 101.981,70.231 101.854,70.358 101.727,70.739 100.838,70.739 100.711,70.739 100.711,71.755 101.092,72.009 101.854,72.009 101.981,72.136 101.981,72.263 101.981,72.517 101.981,73.787
SGND on Top Layer "SGND" (solid, remove dead copper, pour order 16): 94.615,79.756 94.615,79.502 94.615,78.105 94.869,77.851 96.266,77.851 96.52,77.597 96.901,77.216 96.901,76.835 96.901,76.708 97.282,76.2 97.282,76.073 97.282,75.565 97.282,75.438 97.409,75.311 98.044,74.676 100.584,74.676 100.584,75.311 100.965,75.692 104.14,75.819 104.267,75.946 104.267,76.073 104.267,78.105 104.267,78.232 104.013,78.994 101.6,78.994 100.965,79.629 100.965,81.788 100.838,81.915 99.441,81.915 99.187,81.661 99.187,80.137 98.806,79.756
VDD on Top Layer "VDD" (solid, remove dead copper, pour order 14): 98.806,80.137 98.552,80.01 96.774,80.01 96.52,80.137 94.488,80.137 94.488,81.407 94.615,81.534 96.52,81.534 96.52,81.661 96.647,81.788 96.647,82.296 97.282,82.931 97.282,83.185 97.282,83.439 97.536,83.693 97.536,84.709 97.79,84.709 99.568,86.487 100.457,87.376 100.584,87.376 100.584,88.519 101.092,89.027 101.219,89.154 101.473,89.154 101.854,89.535 102.362,89.535 102.743,89.916 102.87,90.043 103.505,90.043 104.013,90.551 104.648,90.551 104.775,90.551 105.029,90.805 113.411,90.805 113.411,90.17 113.919,89.662 114.173,89.662 114.3,89.662 114.427,89.535 114.554,89.408 114.935,89.408 115.951,89.408 116.078,89.281 116.205,89.154 116.205,88.519 116.205,87.249 116.332,87.122 117.094,87.122 117.348,87.122 117.475,86.995 117.475,84.963 117.221,84.709 115.951,84.709 115.57,85.09 113.411,87.249 113.411,87.376 109.474,87.376 109.093,86.995 108.966,86.868 108.966,86.614 101.854,86.614 100.838,85.344 100.711,85.217 100.711,82.296 100.584,82.169 98.933,82.169 98.933,80.264 98.679,80.01
SGND on Top Layer "SGND" (solid, remove dead copper, pour order 32): 105.664,82.296 106.172,81.788 106.172,80.137 105.918,79.883 105.664,79.629 104.14,79.629 102.235,79.629 101.854,80.01 101.854,82.042 102.108,82.296 105.664,82.296

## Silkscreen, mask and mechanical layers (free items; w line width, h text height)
Top Overlay:
  lines w0.254: 109.855,59.182 ccw(c109.855,75.058) 113.964,59.723
  text "VDD" at 96.647,80.391 h0.6
  text "GND" at 96.647,78.359 h0.6
  text "BRA" at 96.774,76.581 h0.6
  text "VSP" at 96.647,74.549 h0.6
  text "DIR" at 96.774,72.771 h0.6
  text "PWM" at 96.647,70.612 h0.6
  text "FG" at 96.774,68.707 h0.6
Bottom Overlay:
  text "B" at 111.125,89.535 h0.51
  text "C" at 99.695,85.852 h0.51
  text "A" at 123.571,81.534 h0.51
Mechanical 1:
  circle w0.203: c109.296,75.438 r3.9
  lines w0.203: 104.469,60.079 cw(c109.296,75.438) 94.428,69.263 94.428,82.578 96.228,81.648 97.333,83.68 96.032,84.564 cw(c109.296,75.438) 98.345,87.24 98.873,86.712 ccw(c99.206,87.044) 99.538,86.712 100.017,87.191 ccw(c99.685,87.523) 100.017,87.856 99.59,88.283 cw(c109.296,75.438) 105.562,91.099 ; 104.469,60.082 114.133,60.082 ccw(c109.296,75.438) 124.626,70.518 124.626,80.399 ; 105.564,91.097 113.97,91.097 113.627,90.056 114.871,89.535 115.188,90.421 cw(c109.296,75.438) 122.623,84.471 121.349,83.795 121.349,83.629 122.187,82.004 122.428,81.978 123.767,82.495 cw(c109.296,75.438) 124.606,80.419 ; 107.975,60.117 107.975,60.833 cw(c108.445,60.833) 108.445,61.303 110.02,61.303 cw(c110.02,60.896) 110.426,60.896 110.426,60.155 ccw(c110.465,60.155) 110.465,60.117 ; 124.583,77.452 cw(c124.269,78.245) 124.626,79.019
